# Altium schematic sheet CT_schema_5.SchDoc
size 368 x 243 mm
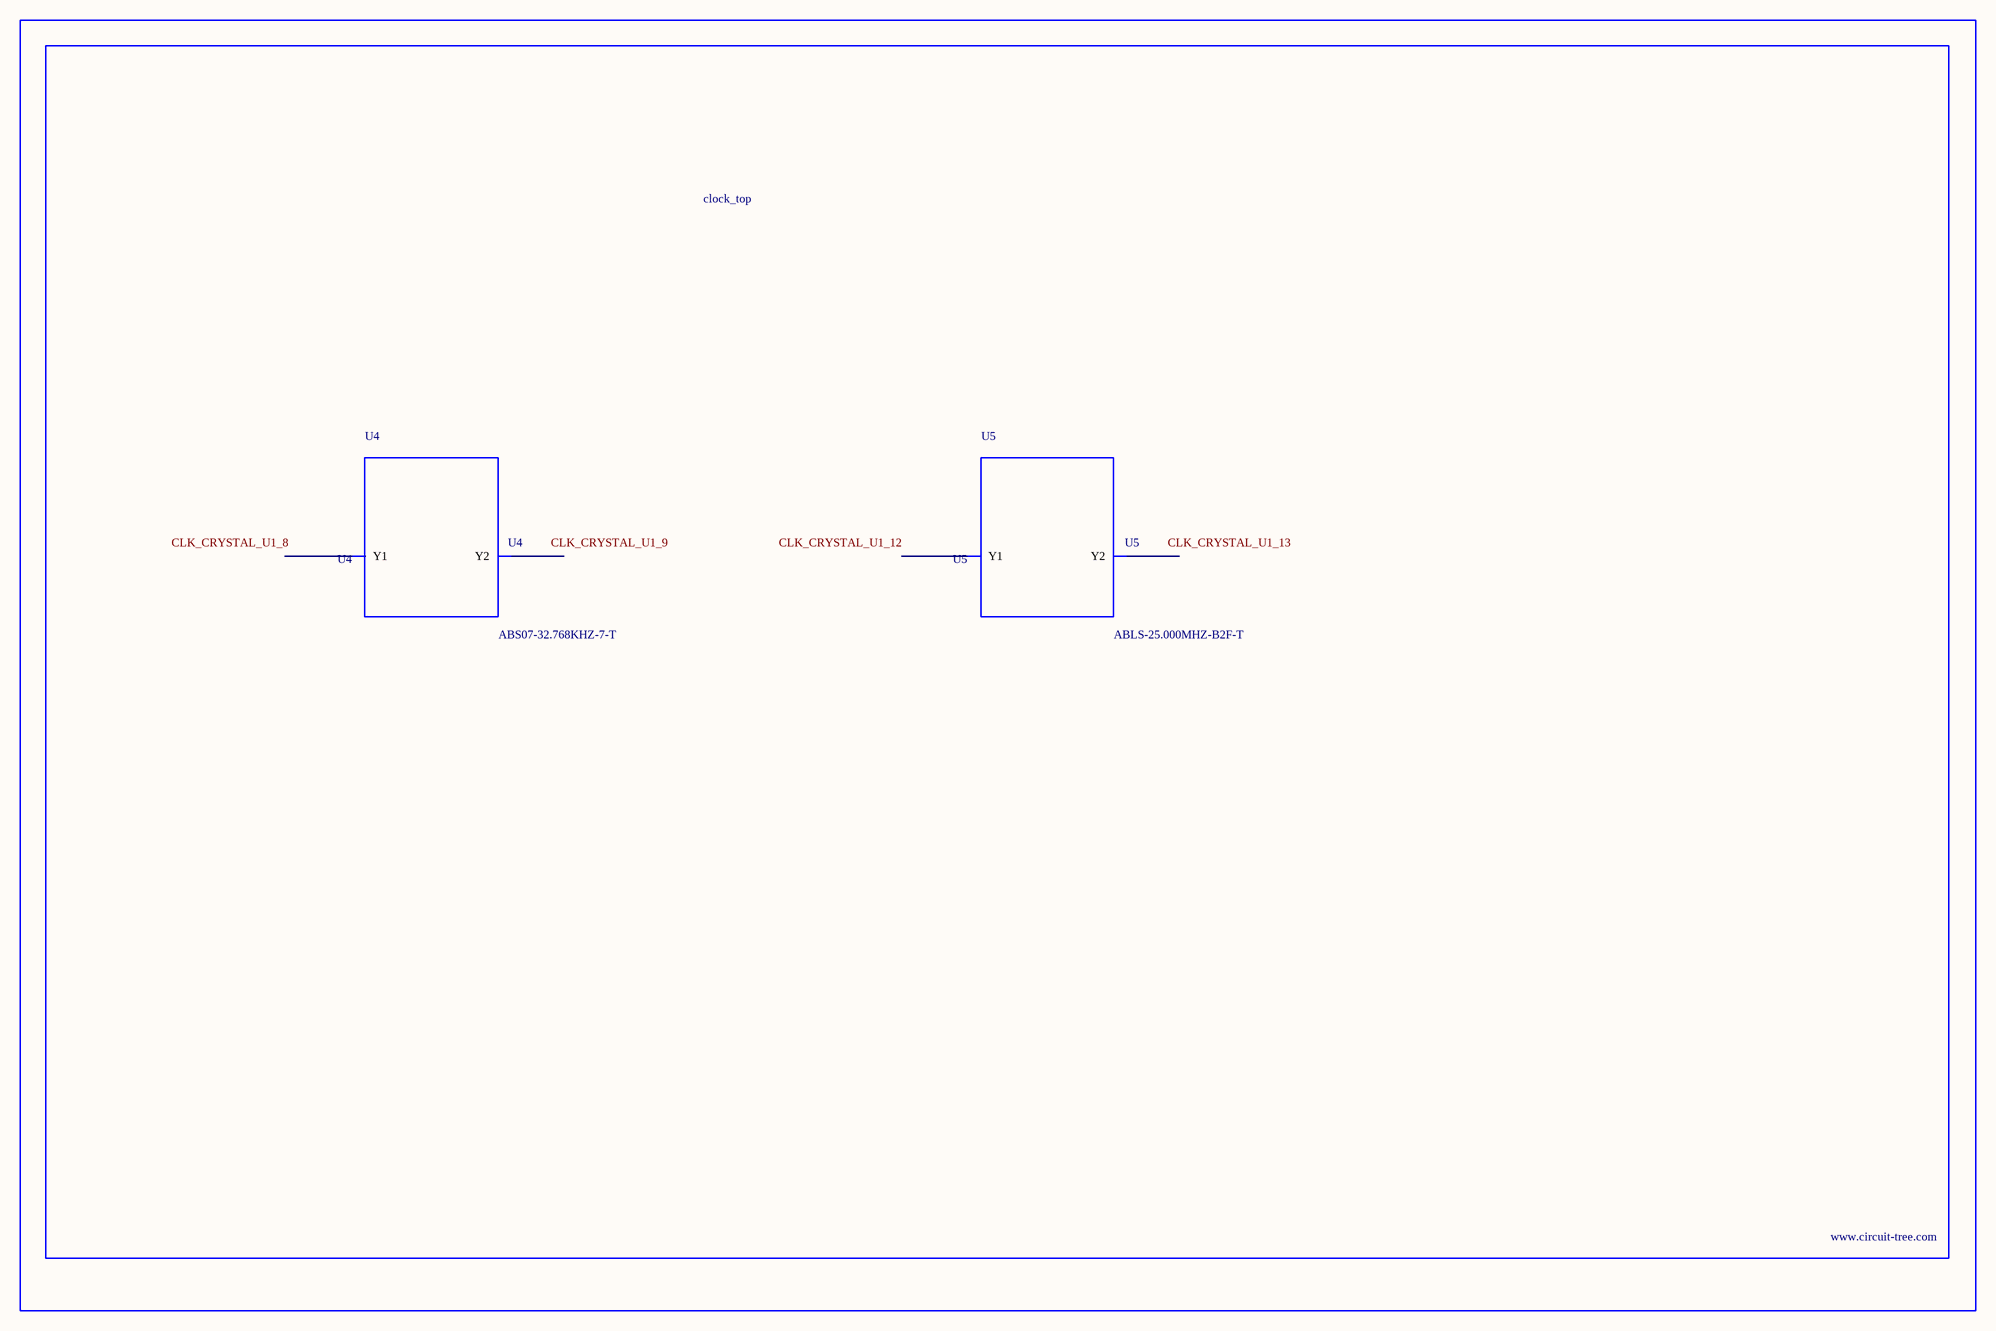
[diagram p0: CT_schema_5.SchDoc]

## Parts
BORDER4  (no value)
U4  ABS07-32.768KHZ-7-T  [ABS07-32.768KHZ-7-T]
U5  ABLS-25.000MHZ-B2F-T  [ABLS-25.000MHZ-B2F-T]

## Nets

Not connected (* = marked no-connect by the designer): U4 1(Y1) 2(Y2); U5 1(Y1) 2(Y2)

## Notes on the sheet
- Labels drawn without touching a wire or pin: CLK_CRYSTAL_U1_8, CLK_CRYSTAL_U1_9, CLK_CRYSTAL_U1_12, CLK_CRYSTAL_U1_13

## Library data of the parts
BORDER4 = BORDER_PAGE4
